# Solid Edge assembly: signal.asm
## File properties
Author: Wir
Template: Normal.asm
Last saved by: administrator
Revision: 5
Application: Solid Edge
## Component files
Grundplatte.par
tze.par
Kurbel.par
welle.par
Umlenkhebel.par
Anlenkhebel.par
Traverse.par
welle lang.par
Signal.par
Traverse oben.par
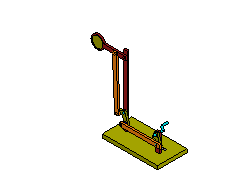
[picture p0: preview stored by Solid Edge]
